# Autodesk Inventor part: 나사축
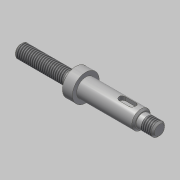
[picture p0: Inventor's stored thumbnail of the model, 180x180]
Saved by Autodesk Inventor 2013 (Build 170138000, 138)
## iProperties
Created: 2019-10
Part Number: 나사축
Material: 강철, 연강
Document SubType Name: Modeling
Designer: mduedu
Density: 1 g/cm^3
Author: mduedu
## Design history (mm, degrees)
sketch "스케치1"
  geometry: L1 (0, 0)-(33, 0); L2 (33, 0)-(33, 4); L3 (33, 4)-(0, 4); L4 (0, 4)-(0, 0); L5 (33, 0)-(39, 0); L6 (39, 0)-(39, 8); L7 (39, 8)-(33, 8); L8 (33, 8)-(33, 0); L9 (39, 0)-(73, 0); L10 (73, 0)-(73, 5.5); L11 (73, 5.5)-(39, 5.5); L12 (39, 5.5)-(39, 0); L13 (73, 0)-(83, 0); L14 (83, 0)-(83, 4); L15 (83, 4)-(73, 4); L16 (73, 4)-(73, 0)
  constraints: 32 end point, 8 parallel, 4 horizontal, 4 perpendicular
  dimensions: "d0" = 83 distance between parallel lines of L14 L4; "d2" = 8 diameter of L15 L13; "d3" = 11 diameter of L11 L9; "d4" = 16 diameter of L7 L5; "d5" = 8 diameter of L3 L1; "d6" = 33 distance of L2.end L3.end; "d7" = 6 distance of L6.end L7.end; "d8" = 40 distance between parallel lines of L10 L8
revolve "회전1" sketch "스케치1" stored, may be unused: angle "d9" = 90 deg
sketch "스케치2"
  geometry: L1 (0, 4)-(0, -4) reference; L2 (0, -4)-(-33, -4) reference; L3 (-33, -4)-(-33, -8) reference; L4 (-33, -8)-(-39, -8) reference; L5 (-39, -8)-(-39, -5.5) reference; L6 (-39, -5.5)-(-73, -5.5) reference; L7 (-73, -5.5)-(-73, -4) reference; L8 (-73, -4)-(-83, -4) reference; L9 (-83, -4)-(-83, 4) reference; L10 (-83, 4)-(-73, 4) reference; L11 (-73, 4)-(-73, 5.5) reference; L12 (-73, 5.5)-(-39, 5.5) reference; L13 (-39, 5.5)-(-39, 8) reference; L14 (-39, 8)-(-33, 8) reference; L15 (-33, 8)-(-33, 4) reference; L16 (-33, 4)-(0, 4) reference; L17 (0, 0)-(-83, 0); L18 (-31, 3)-(-33, 3); L19 (-33, 3)-(-33, 4); L20 (-31, 3)-(-29.268, 4); L21 (-33, 4)-(-29.268, 4)
  constraints: 10 end point, 1 collinear, 1 midpoint, 1 point on line, 1 vertical
  dimensions: "d13" = 1 distance between parallel lines of L18 L21; "d15" = 30 deg angle of L16 L20; "d17" = 2 distance of L18.start L18.end
revolve "회전2" sketch "스케치2" stored, may be unused: angle "d12" = 90 deg
feature "스레드1" dims "d18" = 10, "d19" = 0
feature "스레드2" dims "d20" = 7, "d21" = 0
chamfer "모따기1" distance "d22" = 1; stored, may be unused: second distance "d23" = 2, angle "d24" = 30 deg
chamfer "모따기2" distance "d25" = 1; stored, may be unused: second distance "d26" = 2, angle "d27" = 30 deg
sketch "스케치3"
  geometry: L1 (-31, -3)-(-33, -3) reference; L2 (-33, -3)-(-33, -8) reference; L3 (-33, -8)-(-39, -8) reference; L4 (-39, -8)-(-39, -5.5) reference; L5 (-39, -5.5)-(-72, -5.5) reference; L6 (-72, -5.5)-(-73, -4.5) reference; L7 (-73, -4.5)-(-73, -4) reference; L8 (-73, -4)-(-82, -4) reference; L9 (-82, -4)-(-83, -3) reference; L10 (-83, -3)-(-83, 3) reference; L11 (-83, 3)-(-82, 4) reference; L12 (-82, 4)-(-73, 4) reference; L13 (-73, 4)-(-73, 4.5) reference; L14 (-73, 4.5)-(-72, 5.5) reference; L15 (-72, 5.5)-(-39, 5.5) reference; L16 (-39, 5.5)-(-39, 8) reference; L17 (-39, 8)-(-33, 8) reference; L18 (-33, 8)-(-33, 3) reference; L19 (-33, 3)-(-31, 3) reference; L20 (-31, 3)-(-29.268, 4) reference; L21 (-29.268, 4)-(-1, 4) reference; L22 (-1, 4)-(0, 3) reference; L23 (0, 3)-(0, -3) reference; L24 (0, -3)-(-1, -4) reference; L25 (-1, -4)-(-29.268, -4) reference; L26 (-29.268, -4)-(-31, -3) reference; L27 (-59, 5.5)-(-69, 5.5); L28 (-69, 5.5)-(-69, 3); L29 (-69, 3)-(-59, 3); L30 (-59, 3)-(-59, 5.5); 1 further point
  constraints: 8 end point, 2 parallel, 1 horizontal, 1 perpendicular, 1 point on line
  dimensions: "d28" = 20 distance between parallel lines of L30 L16; "d29" = 10 distance of L27.start L27.end; "d30" = 2.5 distance of L27.end L28.end
extrude "돌출1" cut sketch "스케치3" stored distance "d31" = 4; taper "d32" = 0 deg
fillet "모깎기1"
fillet "모깎기2"
node "솔리드1"
node "절단 모서리 투영1"
node "절단 모서리 투영2"
